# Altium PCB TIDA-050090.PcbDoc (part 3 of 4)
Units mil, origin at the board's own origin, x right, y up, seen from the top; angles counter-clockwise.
Board outline 4150 x 4140 mil, 8 copper layers (Top Layer 1, POWER1, GND1, SIGNAL1, SIGNAL2, GND2, POWER2, Bottom Layer 1), stack 60.703 mil thick; 130 components, 39 nets, 355 pads, 2292 vias.
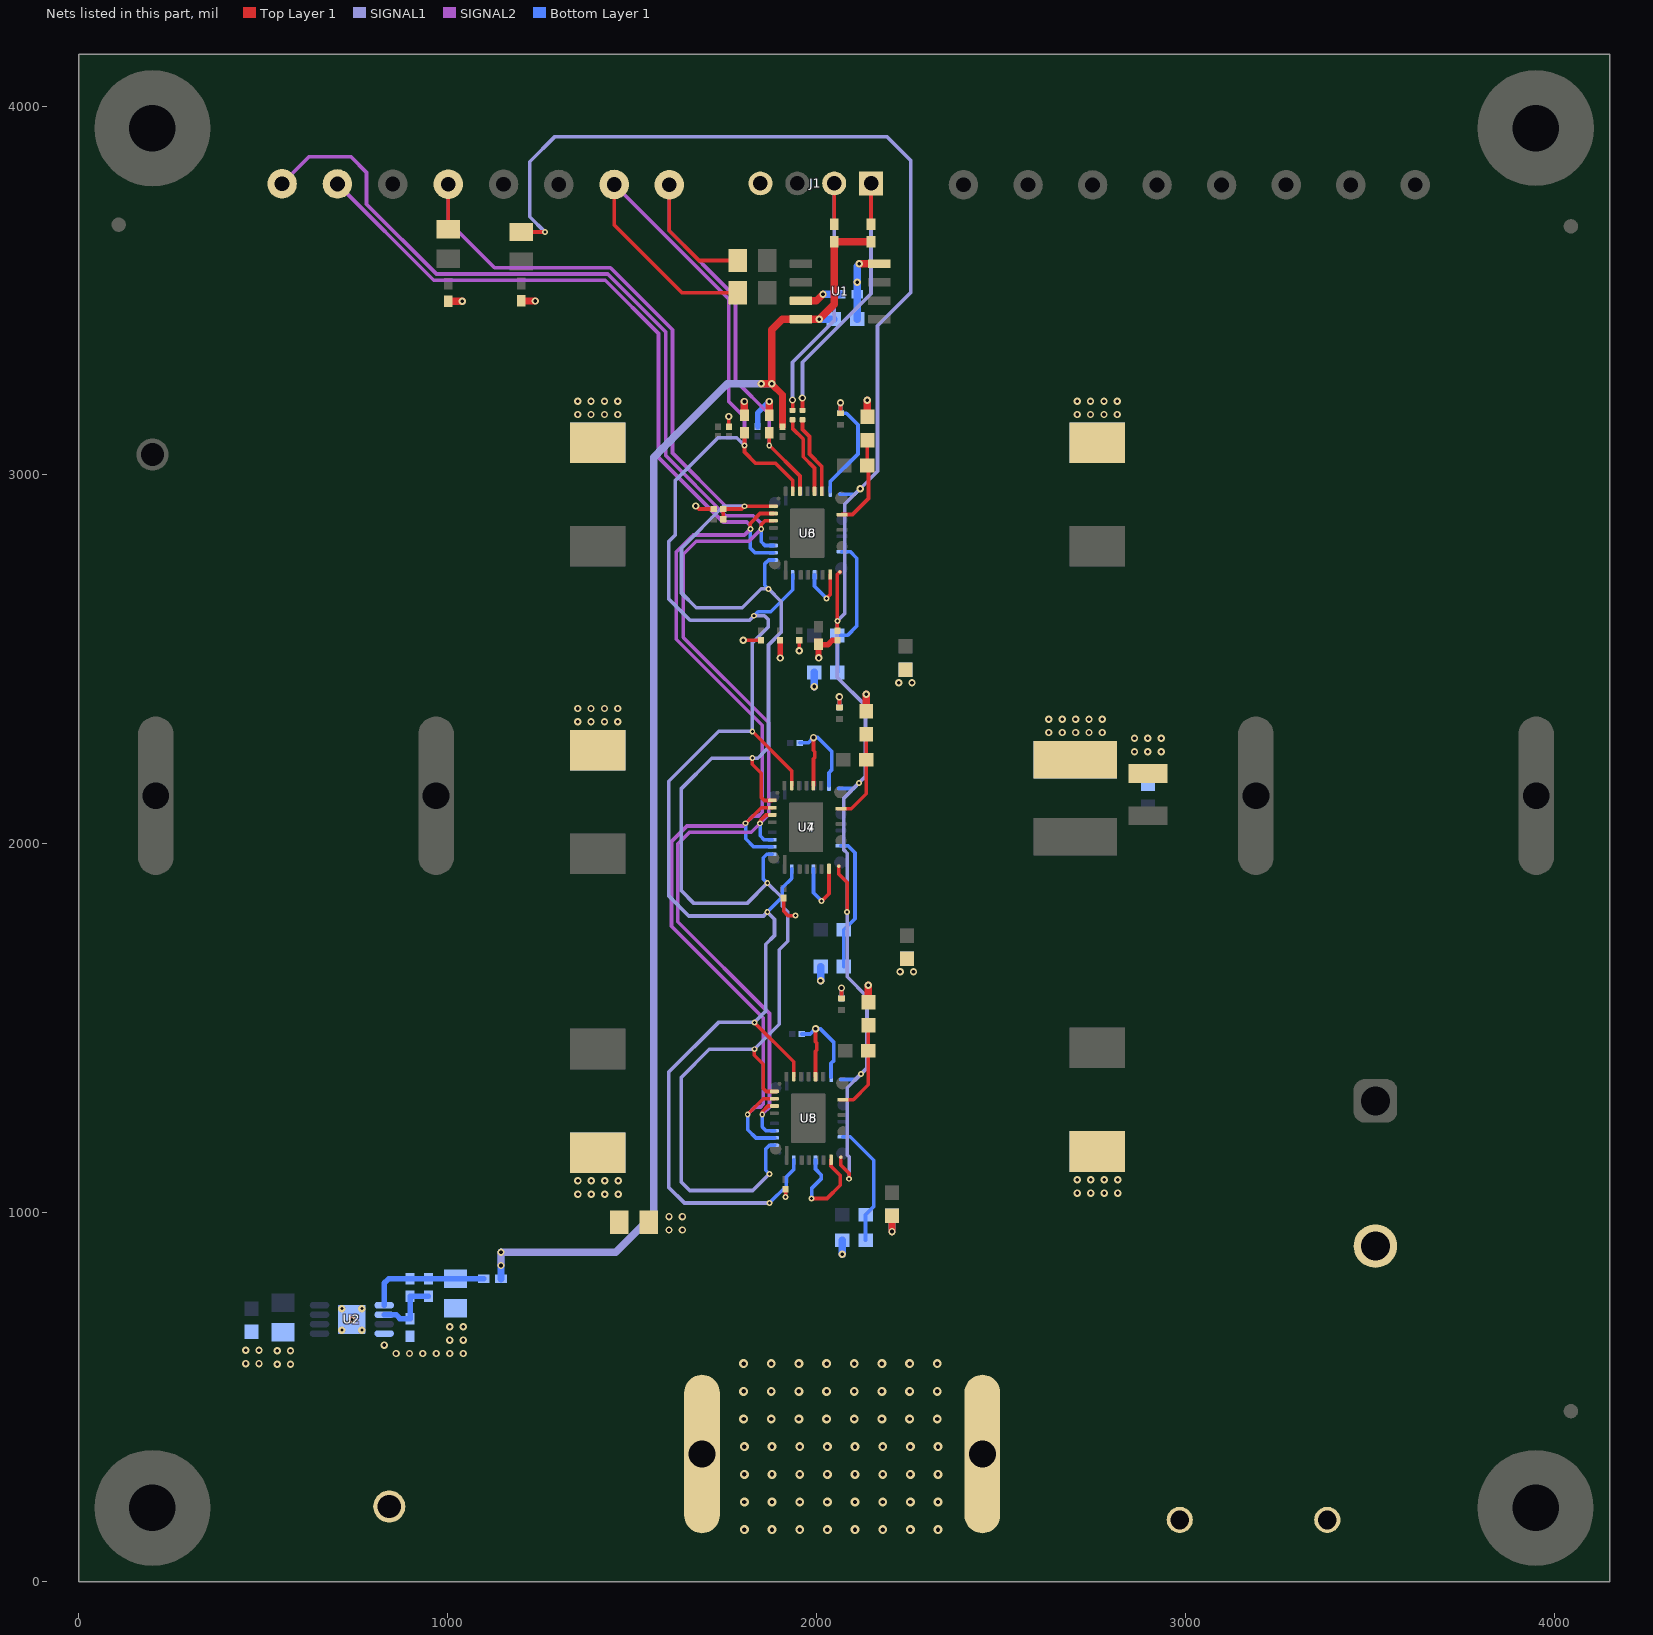
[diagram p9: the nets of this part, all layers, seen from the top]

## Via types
v1: diameter 24, hole 12, Top Layer 1 to Bottom Layer 1, tented both sides, 1740 vias
v2: diameter 20, hole 10, Top Layer 1 to Bottom Layer 1, tented both sides, 444 vias
v3: diameter 16, hole 8, Top Layer 1 to Bottom Layer 1, tented both sides, 67 vias
v4: diameter 19.68, hole 7.87, Top Layer 1 to Bottom Layer 1, tented both sides, 41 vias

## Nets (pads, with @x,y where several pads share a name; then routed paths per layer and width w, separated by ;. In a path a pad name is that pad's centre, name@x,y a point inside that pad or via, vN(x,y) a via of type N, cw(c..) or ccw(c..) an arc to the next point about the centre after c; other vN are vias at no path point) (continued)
ITIMER: C2.1 ITIMER1.1 NT1.1 U3.14 | length 1355.3
  Top Layer 1 w10: ITIMER1.1@1600.98,3786.57 1600.98,3662.17 1681.74,3581.41 NT1.1@1786.6,3581.41 ; C2.1@1872.04,3114.53 v3(1872.04,3080.35) 1955.31,2997.08 U3.14@1955.31,2955.69
  SIGNAL2 w10: ITIMER1.1@1600.98,3786.57 1600.98,3662.17 1780.4,3482.75 1780.4,3256.16 1872.04,3164.51 v3(1872.04,3080.35)
NetC6_1: C6.1 C7.1 R19.2 RZ2.2 U2.1 | length 334.2
  Bottom Layer 1 w15: U2.1@828.14,749.25 828.14,808.99 840.07,820.92 C6.1@898.24,820.92 R19.2@948.26,820.92 C7.1@1021.44,820.92 RZ2.2@1097.63,820.92
NetC6_2: C6.2 R19.1 R20.2 U2.2 | length 185.3
  Bottom Layer 1 w15: U2.2@828.14,723.66 860.27,723.66 870.98,712.95 R20.2@898.24,712.95 C6.2@898.24,773.68 R19.1@948.26,773.68
NetR23_2: R23.2 U3.12 | length 218.7
  Top Layer 1 w10: R23.2@1935.32,3149.76 1935.32,3125.86 1963.94,3097.24 1963.94,3049.72 1994.68,3018.98 U3.12@1994.68,2955.69
NetR24_2: R24.2 U3.11 | length 215.8
  Top Layer 1 w10: R24.2@1961.97,3149.76 1961.97,3123.25 1980.94,3104.28 1980.94,3056.76 2014.37,3023.33 U3.11@2014.37,2955.69
NetRZ1_2: RZ1.2 U1.7 | length 112.4
  Top Layer 1 w20: U1.7@1957.91,3472.53 2000,3472.53 v2(2017.71,3490.23)
  Bottom Layer 1 w20: v2(2017.71,3490.23) RZ1.2@2062.98,3490.23
OVP: NT4.1 OV1.1 R1.1 R11.2 U3.18 U4.18 U5.18 U6.18 U7.18 U8.18 | length 5503.5
  Top Layer 1 w10: NT4.1@1001.57,3666.22 1001.9,3666.55 OV1.1@1001.9,3788.49 ; R1.1@1747.28,2879.9 R11.2@1747.28,2907.71 1796.92,2907.71 v3(1804.54,2915.33) U3.18@1883.46,2915.33 ; v3(1826.01,2232.32) 1826.01,2215.9 1850.39,2191.53 1850.39,2125.84 1850.34,2125.8 1858.3,2117.83 U4.18@1880.51,2117.83 ; v3(1831.58,1443.38) 1831.58,1426.96 1855.95,1402.59 1855.95,1336.9 1855.91,1336.85 1863.87,1328.89 U5.18@1886.08,1328.89
  SIGNAL1 w10: v3(1804.54,2915.33) 1747.65,2915.33 1634.06,2801.74 1634.06,2679.82 1673.97,2639.91 1798.69,2639.91 1850.21,2691.43 v3(1869.67,2691.43) 1904.86,2656.25 1904.86,2574.15 1870.08,2539.37 1870.08,2261.71 1840.7,2232.32 v3(1826.01,2232.32) 1715.83,2232.32 1633.86,2150.36 1633.86,1872.68 1667.82,1838.72 1811.52,1838.72 v3(1866.73,1893.93) 1906.97,1853.69 1906.97,1830.84 1922.16,1815.66 1922.16,1735.77 1899.32,1712.94 1899.32,1511.12 v3(1831.58,1443.38) 1709.7,1443.38 1633.86,1367.54 1633.86,1082.77 1656.38,1060.25 1827.54,1060.25 v3(1872.28,1104.99)
  SIGNAL2 w10: OV1.1@1001.9,3788.49 1001.9,3687.45 1127.55,3561.79 1441.35,3561.79 1609.64,3393.5 1609.64,3059.71 1754.02,2915.33 v3(1804.54,2915.33)
  Bottom Layer 1 w10: v3(1866.73,1893.93) 1855.68,1904.99 1855.68,1962.32 1865.52,1972.17 U7.18@1880.53,1972.17 ; v3(1869.67,2691.43) 1859.65,2701.45 1859.65,2757.9 1859.65,2758.72 1860.62,2759.69 1860.62,2759.82 1870.46,2769.67 U6.18@1883.46,2769.67 ; v3(1872.28,1104.99) 1862.27,1115.01 1862.27,1173.05 1872.44,1183.22 U8.18@1886.08,1183.22
PGND: C5.2 C7.2 C20.2 C21.2 C22.1 C23.1 C24.2 C25.2 D1.2 D2.2 D3.2 D4.2 D5.2 D6.2 D7.2 D8.2 D9.2 D10.2 J5.1 R20.1 RCH1.2 TP2.1 U2.4 U2.9
  other v1: 1804.54,140.97 1879.54,140.97 1954.54,140.97 2029.54,140.97 2104.54,140.97 2179.54,140.97 2254.54,140.97 2329.54,140.97 1804.54,215.97 1879.54,215.97 1954.54,215.97 2029.54,215.97 2104.54,215.97 2179.54,215.97 2254.54,215.97 2329.54,215.97 1804.54,290.97 1879.54,290.97 1954.54,290.97 2029.54,290.97 2104.54,290.97 2179.54,290.97 2254.54,290.97 2329.54,290.97 1804.54,365.97 1879.54,365.97 1954.54,365.97 2029.54,365.97 2104.54,365.97 2179.54,365.97 2254.54,365.97 2329.54,365.97 1802.54,440.97 1877.54,440.97 1952.54,440.97 2027.54,440.97 2102.54,440.97 2177.54,440.97 2252.54,440.97 2327.54,440.97 1802.54,515.97 1877.54,515.97 1952.54,515.97 2027.54,515.97 2102.54,515.97 2177.54,515.97 2252.54,515.97 2327.54,515.97 1802.54,590.97 1877.54,590.97 1952.54,590.97 2027.54,590.97 2102.54,590.97 2177.54,590.97 2252.54,590.97 2327.54,590.97
  other v2: 537.91,589.48 574.25,589.48 452.63,591.16 488.97,591.16 860.43,618.54 896.78,618.54 933.12,618.54 969.47,618.54 1005.82,618.54 1042.16,618.54 537.91,625.83 574.25,625.83 452.63,627.5 488.97,627.5 828.14,641.33 1005.82,654.89 1042.16,654.89 1005.82,691.24 1042.16,691.24 1353.32,1050.19 1389.67,1050.19 1426.01,1050.19 1462.36,1050.19 2707.38,1053.36 2743.73,1053.36 2780.07,1053.36 2816.42,1053.36 1353.32,1086.53 1389.67,1086.53 1426.01,1086.53 1462.36,1086.53 2707.38,1089.7 2743.73,1089.7 2780.07,1089.7 2816.42,1089.7 2862.14,2249.66 2898.48,2249.66 2934.83,2249.66 2862.14,2286.01 2898.48,2286.01 2934.83,2286.01 2629.71,2301.9 2666.06,2301.9 2702.4,2301.9 2738.75,2301.9 2775.1,2301.9 1352.58,2330.75 1388.93,2330.75 1425.28,2330.75 1461.62,2330.75 2629.71,2338.25 2666.06,2338.25 2702.4,2338.25 2738.75,2338.25 2775.1,2338.25 1352.58,2367.09 1388.93,2367.09 1425.28,2367.09 1461.62,2367.09 1352.58,3163.94 1388.93,3163.94 1425.28,3163.94 1461.62,3163.94 2706.66,3163.94 2743,3163.94 2779.35,3163.94 2815.7,3163.94 1352.58,3200.28 1388.93,3200.28 1425.28,3200.28 1461.62,3200.28 2706.66,3200.28 2743,3200.28 2779.35,3200.28 2815.7,3200.28
  other v4: 713.38,681.73 767.71,681.73 740.54,710.86 713.38,740 767.71,740
PGOOD: PGOOD1.1 U3.19 U4.19 U5.19 U6.19 U7.19 U8.19 | length 4520.8
  Top Layer 1 w10: v3(1808.08,2055.87) 1850.35,2098.15 U4.19@1880.51,2098.15 ; v3(1813.63,1266.93) 1855.91,1309.21 U5.19@1886.08,1309.21 ; v3(1820.86,2853.37) 1820.86,2869.45 1847.06,2895.65 U3.19@1883.46,2895.65
  SIGNAL2 w10: PGOOD1.1@701.45,3788.96 962.62,3527.79 1427.27,3527.79 1571.71,3383.35 1571.71,3047.55 1746.92,2872.34 1811.02,2872.34 1820.86,2862.5 v3(1820.86,2853.37) 1804.65,2837.17 1666.87,2837.17 1663.78,2834.08 1662.95,2834.08 1620.06,2791.19 1620.06,2554.72 1853.05,2321.73 1853.05,2086.03 1842.84,2075.83 1828.03,2075.83 v3(1808.08,2055.87) 1800.93,2048.73 1648.93,2048.73 1607.01,2006.81 1607.01,1776.58 1855.55,1528.04 1855.55,1294.04 1848.4,1286.88 1833.58,1286.88 v3(1813.63,1266.93)
  Bottom Layer 1 w10: v3(1808.08,2055.87) 1808.08,2014.01 1830.24,1991.85 U7.19@1880.53,1991.85 ; v3(1813.63,1266.93) 1813.63,1225.07 1835.79,1202.91 U8.19@1886.08,1202.91 ; v3(1820.86,2853.37) 1820.86,2801.67 1833.18,2789.35 U6.19@1883.46,2789.35
PMBUS_SCL: J1.2 R14.1 R23.1 | length 773.1
  Top Layer 1 w10: R23.1@1935.32,3175.35 v2@1935.32,3203.74 ; R14.1@2048.02,3679.86 J1.2@2048.02,3790.57
  SIGNAL1 w10: v2(1934.97,3203.38) 1934.97,3305.91 2048.02,3418.97 J1.2@2048.02,3790.57
PMBUS_SDA: J1.1 R13.1 R24.1 | length 802.9
  Top Layer 1 w10: R24.1@1961.97,3175.35 v2(1961.97,3208.74) ; R13.1@2148.02,3679.96 J1.1@2148.02,3790.57
  SIGNAL1 w10: v2(1961.97,3208.74) 1961.97,3305.37 2011.62,3355.02 2148.02,3491.42 J1.1@2148.02,3790.57
QGND1: C1.2 C2.2 C3.2 C4.2 C8.1 C9.1 C10.2 C11.2 C12.2 C13.2 C14.1 C15.1 C16.2 C17.2 C18.2 C19.2 C26.1 C27.1 C28.2 C29.2 C30.2 C31.2 J1.4 J2.1 J2.2 R3.1 R4.1 R5.1 R6.1 R7.1 R8.1 R9.1 R10.1 R11.1 R12.1 R15.1 R17.1 R18.1 RCH1.1 RZ1.1 U1.4 U3.5 U4.5 U4.12 U5.5 U5.12 U6.5 U6.12 U7.5 U7.12 U8.5 U8.12 | length 2919.6
  Top Layer 1 w10: v2(1672.49,2915.98) 1680.76,2907.71 R11.1@1721.29,2907.71 ; R12.1@1762.39,3130.59 v2@1762.39,3158.97 ; v2(1801.18,2551.86) R4.1@1850,2551.86 ; R7.1@1911.02,1853.12 1911.02,1817.64 1923.19,1805.47 v3(1943.63,1805.47) ; v3(1916.59,1042.22) R5.1@1916.59,1064.17 ; v2@1953.35,2523.48 R3.1@1953.35,2551.86 ; v3(1986.85,1038.85) 2028.73,1038.85 2064.3,1074.42 2064.3,1101.17 2039.62,1125.85 U5.5@2039.62,1143.85 ; U4.12@1991.73,2158.19 1991.73,2230.6 1995.39,2234.26 1995.39,2250 1991.73,2253.66 1991.73,2287.86 v2(1992.09,2288.21) ; U5.12@1997.3,1369.25 1997.3,1437.18 2000.94,1440.82 2000.94,1461.05 1997.64,1464.36 v2(1997.64,1499.27) ; v3(2014.14,1845.09) 2034.06,1865.01 U4.5@2034.06,1932.8 ; v3(2027.55,2665.59) 2037.01,2675.05 U3.5@2037.01,2730.3 ; C9.1@2062.29,2370.06 v2(2062.29,2398.38) ; C8.1@2065.25,3167.56 v2(2065.25,3195.88) ; C14.1@2067.86,1581.11 v2(2067.86,1609.44)
  Top Layer 1 w15: v2(1901.67,2503.8) R10.1@1901.67,2551.86 ; v2@2005.49,2503.8 C1.2@2005.49,2541.23 2006.87,2539.86 2030.71,2539.86 2042.72,2551.86 R15.1@2056.69,2551.86
  Top Layer 1 w20: R18.1@1001.57,3470.71 v2(1039.56,3470.71) ; R17.1@1199.55,3471.84 v2(1237.54,3471.84) ; C3.2@1804.68,3161.77 v2(1804.68,3199.2) ; C2.2@1872.04,3161.77 v2(1872.04,3199.2) ; v2(2116.38,3572.53) U1.4@2170.51,3572.53 ; C13.2@2135.13,2359.89 v2(2135.13,2405.49) ; C12.2@2138.08,3157.39 v2(2138.08,3202.99) ; C18.2@2140.69,1570.95 v2(2140.69,1616.55) ; v2(2204.87,949.05) C16.2@2204.87,991.49
  Bottom Layer 1 w10: R6.1@1954.74,2273.8 1977.67,2273.8 v2(1992.09,2288.21) 2003.77,2288.21 2041.05,2250.93 2041.05,2200.06 2034.07,2193.07 U7.5@2034.07,2157.2 ; R9.1@1960.29,1484.86 1983.23,1484.86 v2(1997.64,1499.27) 2009.61,1499.27 2047.25,1461.63 2047.25,1412.67 2039.62,1405.05 U8.5@2039.62,1368.26 ; v3(1986.85,1038.85) 1986.85,1065.84 2012.64,1091.63 2012.64,1103.13 1997.3,1118.47 U8.12@1997.3,1142.87 ; U7.12@1991.75,1931.81 1991.75,1867.48 v3(2014.14,1845.09) ; U6.12@1994.68,2729.31 1994.69,2698.45 v3(2027.55,2665.59) ; U6.5@2037.01,2954.7 2037.01,2981.45 2112.65,3057.09 2112.65,3136.06 2081.16,3167.56 C15.1@2065.25,3167.56 v2(2065.25,3195.88) ; C26.1@2062.29,2370.06 v2(2062.29,2398.38) ; C27.1@2067.86,1581.11 v2(2067.86,1609.44)
  Bottom Layer 1 w15: R8.1@1840.51,3131.45 1840.51,3167.67 v2(1872.04,3199.2)
  Bottom Layer 1 w20: v2(1993.7,2426.45) C19.2@1993.7,2464.8 ; v2(2011.16,1629.35) C30.2@2011.16,1667.7 ; v2(2070.13,887.23) C31.2@2070.13,925.59 ; C4.2@2110.23,3422.53 RZ1.1@2110.23,3490.23 v2(2110.23,3522.53) 2110.23,3566.38 v2(2116.38,3572.53) ; v2(2204.87,949.05) C29.2@2204.87,991.49
  other v2: 1600.27,953.36 1636.61,953.36 1600.27,989.71 1636.61,989.71 2226.66,1653.05 2263.01,1653.05 2222.73,2437.2 2259.07,2437.2 2005.85,2504.16 1953.7,2523.83 1762.04,3158.62
SFT_SEL: NT3.1 R15.2 U3.6 U4.6 U5.6 U6.6 U7.6 U8.6 | length 4855.9
  Top Layer 1 w10: NT3.1@1199.55,3658.69 v3(1264.37,3658.69) ; R15.2@2056.69,2577.85 v3(2056.69,2604.23) 2056.69,2730.3 U3.6@2063.58,2737.19 ; U4.6@2060.63,1939.68 2060.63,1918.06 2083.19,1895.5 v3(2083.19,1815.77) ; U5.6@2066.2,1150.74 2066.2,1129.11 2088.76,1106.55 v3(2088.76,1092.11)
  SIGNAL1 w10: v3(1264.37,3658.69) 1222.68,3700.38 1222.68,3849.02 1290.98,3917.32 2190.7,3917.32 2255.47,3852.56 2255.47,3494.69 2165.35,3404.57 2165.35,3009.89 v2(2118.39,2962.93) 2076.77,2921.31 2076.77,2624.31 v3(2056.69,2604.23) 2056.69,2451.18 2132.75,2375.13 2132.75,2182.72 v3(2115.46,2165.43) 2074.34,2124.31 2074.34,1983.49 2083.19,1974.64 v3(2083.19,1815.77) 2083.19,1639.65 2137.1,1585.74 2137.1,1392.58 v3(2121.01,1376.49) 2083.36,1338.84 2083.36,1156.83 2088.76,1151.44 v3(2088.76,1092.11)
  Bottom Layer 1 w10: U7.6@2060.65,2150.31 2100.34,2150.32 v3(2115.46,2165.43) ; U6.6@2063.58,2947.81 2103.28,2947.82 v2(2118.39,2962.93) ; U8.6@2066.2,1361.37 2105.89,1361.37 v3(2121.01,1376.49)
SWEN: SWEN1.1 U3.20 U4.20 U5.20 U6.20 U7.20 U8.20 | length 4526.6
  Top Layer 1 w10: v3(1847.45,2055.83) v3(1847.45,2055.83) 1847.5,2063.08 1862.88,2078.46 U4.20@1880.51,2078.46 ; v3(1850.39,2853.33) v3(1850.39,2853.33) 1850.43,2865.8 1860.6,2875.96 U3.20@1883.46,2875.96 ; v3(1853,1266.88) 1853.05,1266.93 1853.05,1274.13 1868.44,1289.52 U5.20@1886.08,1289.52
  SIGNAL2 w10: SWEN1.1@551.45,3789.4 624.48,3862.44 738.18,3862.44 780.45,3820.16 780.45,3734 969.66,3544.79 1434.31,3544.79 1591.16,3387.95 1591.16,3052.9 1754.3,2889.75 1828.98,2889.75 1850.39,2868.34 v3(1850.39,2853.33) 1817.23,2820.17 1673.92,2820.17 1639.04,2785.29 1639.04,2559.79 1870.74,2328.08 1870.74,2079.12 v3(1847.45,2055.83) 1823.35,2031.73 1655.97,2031.73 1624.01,1999.76 1624.01,1789.02 1872.55,1540.47 1872.55,1287 1855.44,1269.88 1853,1269.88 v3(1853,1266.88)
  Bottom Layer 1 w10: v3(1847.45,2055.83) 1847.45,2021.77 1857.68,2011.54 U7.20@1880.53,2011.54 ; v3(1850.39,2853.33) 1850.39,2819.27 1860.62,2809.04 U6.20@1883.46,2809.04 ; v3(1853,1266.88) 1853,1232.83 1863.24,1222.59 U8.20@1886.08,1222.59
TEMP: C3.1 NT2.1 TEMP1.1 U3.15 U4.15 U5.15 U6.15 U7.15 U8.15 | length 5767.7
  Top Layer 1 w10: TEMP1.1@1451.62,3787.49 1451.62,3677.55 1635.39,3493.79 NT2.1@1786.6,3493.79 ; C3.1@1804.68,3114.53 v3(1804.68,3080.35) 1804.68,3062.1 1835.29,3031.5 1889.37,3031.5 1935.63,2985.24 U3.15@1935.63,2955.69 ; v3(1826.01,2305.02) 1932.68,2198.36 U4.15@1932.68,2158.19 ; v3(1831.58,1516.07) 1938.24,1409.41 U5.15@1938.24,1369.25
  SIGNAL1 w10: v3(1804.68,3080.35) 1783.92,3101.12 1733.01,3101.12 1617.06,2985.17 1617.06,2837.54 1599.29,2819.76 1599.29,2664.08 1657.45,2605.91 1818.52,2605.91 v3(1831.02,2618.41) 1858.84,2618.41 1869.67,2607.58 1869.67,2588.57 1826.01,2544.91 v3(1826.01,2305.02) 1735.28,2305.02 1599.86,2169.6 1599.86,1858.6 1653.74,1804.72 1856.26,1804.72 v3(1866.73,1815.19) 1886.16,1795.76 1886.16,1751.69 1862.56,1728.09 1862.56,1547.05 v3(1831.58,1516.07) 1734.31,1516.07 1599.86,1381.62 1599.86,1068.69 1642.29,1026.25 v3(1872.28,1026.25)
  SIGNAL2 w10: TEMP1.1@1451.62,3787.49 1762.04,3477.07 1762.04,3199.2 1804.68,3156.56 v3(1804.68,3080.35)
  Bottom Layer 1 w10: v3(1831.02,2618.41) 1841.83,2629.23 1875.94,2629.23 1935.63,2688.92 U6.15@1935.63,2729.31 ; v3(1866.73,1815.19) 1907.58,1856.04 1907.58,1881.37 1932.69,1906.48 U7.15@1932.69,1931.81 ; v3(1872.28,1026.25) 1918.01,1071.98 1918.01,1097.31 1938.24,1117.54 U8.15@1938.24,1142.87
VCC_3v3: C4.1 R13.2 R14.2 R16.2 RZ2.1 U1.8 | length 3830.5
  Top Layer 1 w18: v2(1878.39,3246.97) 1907.91,3217.44 R16.2@1907.91,3130.59
  Top Layer 1 w20: v2(1850.12,3246.97) v2(1878.39,3246.97) 1878.39,3394.13 1906.78,3422.53 U1.8@1957.91,3422.53 v2(2007.87,3422.53) 2048.02,3462.68 R14.2@2048.02,3632.62 2048.12,3632.71 R13.2@2148.02,3632.71
  SIGNAL1 w20: v2(1144.87,856.93) v2(1144.87,893.28) 1456.22,893.28 1558.93,995.98 1558.93,3047.78 1758.12,3246.97 v2(1850.12,3246.97) v2(1878.39,3246.97)
  Bottom Layer 1 w20: RZ2.1@1144.87,820.92 v2(1144.87,856.93) v2(1144.87,893.28) ; v2(2007.87,3422.53) C4.1@2047.24,3422.53
VDD_efuse1: C12.1 R21.1 U3.9 | length 249.2
  Top Layer 1 w10: U3.9@2069.49,2892.7 2097.53,2892.7 2141.3,2936.47 2141.3,3022.28 R21.1@2138.08,3025.51 C12.1@2138.08,3094.4
VDD_efuse2: C18.1 R25.1 U5.9 | length 246.5
  Top Layer 1 w10: U5.9@2072.1,1306.25 2100.15,1306.25 2140.69,1346.8 R25.1@2140.69,1439.06 C18.1@2140.69,1507.96
VDD_efuse3: C30.1 R27.1 U7.9 | length 366.2
  Bottom Layer 1 w10: U7.9@2066.55,1994.8 2085.31,1994.8 2104.25,1975.86 2104.25,1797.06 R27.1@2074.15,1766.96 C30.1@2074.15,1667.7
VDD_efuse4: C13.1 R22.1 U4.9 | length 246.5
  Top Layer 1 w10: U4.9@2066.54,2095.2 2094.58,2095.2 2135.13,2135.75 R22.1@2135.13,2228.01 C13.1@2135.13,2296.9
VDD_efuse5: C19.1 R26.1 U6.9 | length 393.5
  Bottom Layer 1 w10: R26.1@2057.03,2565.19 2083.85,2565.19 2109.52,2590.86 2109.52,2774.54 2091.76,2792.3 U6.9@2069.49,2792.3 ; C19.1@2057.09,2465.2 R26.1@2057.09,2564.46
VDD_efuse6: C31.1 R28.1 U8.9 | length 335.7
  Bottom Layer 1 w10: U8.9@2072.1,1205.86 2091.94,1205.86 2155.51,1142.28 2155.51,1016.87 R28.1@2133.13,994.48 C31.1@2133.13,925.59
pads on no net: FID1.1 FID2.1 FID3.1 H1.1 H2.1 H3.1 H4.1 H5.0 H6.0 H7.0 H8.0 LBL1.0 U1.1 U1.2 U1.3 U2.3 U2.6 U2.7 U3.17 U3.21 U4.11 U4.14 U4.17 U4.21 U5.11 U5.14 U5.17 U5.21 U6.11 U6.14 U6.17 U6.21 U7.11 U7.14 U7.17 U7.21 U8.11 U8.14 U8.17 U8.21

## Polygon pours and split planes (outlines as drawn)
Efuse_OUT on Top Layer 1 "EFUSE_OUT_L01_P030" (solid, remove dead copper, pour order 30): 2112.88,1299.02 2091.28,1277.41 2061.94,1277.41 2052.89,1268.37 2052.89,1191.13 2059.08,1184.95 2089.86,1184.95 2112.88,1161.92 2112.88,1054.78 2038.21,980.1 2038.21,33.03 2051.32,19.92 4044.62,19.92 4108.4,83.7 4108.4,4025.6 4017.58,4116.42 2134.47,4116.42 2106.89,4088.84 2106.89,2882.09 2088.66,2863.86 2059.32,2863.86 2050.28,2854.81 2050.28,2777.58 2075.59,2752.27 2075.59,2465.31 2104.96,2434.65 2104.96,2085.61 2085.71,2066.36 2056.37,2066.36 2047.32,2057.31 2047.32,1980.08 2058.49,1980.08 2098.55,1940.01 2098.55,1629.27 2112.88,1614.94
Efuse_IN on Top Layer 1 "EFUSE_IN_L01_P029" (solid, remove dead copper, pour order 29): 2089.04,1901.27 2089.04,1615.96 2098.55,1606.45 2098.55,1332.47 2085.14,1319.05 2050.36,1319.05 2024.4,1293.09 2024.4,32.13 2011.66,19.39 53.59,19.39 23.76,49.22 23.76,4064.95 72.98,4114.17 2080.85,4114.17 2095.59,4099.43 2095.59,3057.01 2095.59,2918.57 2082.52,2905.49 2053.5,2905.49 2028.57,2880.56 2028.57,2761.73 2061.79,2728.5 2061.79,2462.21 2092.64,2431.36 2092.64,2121.07 2079.57,2107.99 2044.79,2107.99 2020.39,2083.59 2020.39,1969.93
PGND on Top Layer 1 "PGND_L01_P000" (solid, remove dead copper, pour order 0): 2480.31,634.64 1681.48,634.64 1624.01,577.17 1624.01,109.14 1675.51,57.64 2488.5,57.64 2519.68,88.82 2519.68,595.27
Efuse_OUT on Bottom Layer 1 "EFUSE_OUT_L08_P046" (solid, remove dead copper, pour order 46): 2112.65,3399.02 2112.65,4088.84 2137.98,4114.17 4063.6,4114.17 4114.16,4063.61 4114.16,59.28 4084.41,29.53 2103.25,29.53 2070.6,62.17 2070.6,864.67 2170.34,964.41 2170.34,1144.04 2091.53,1222.85 2062.47,1222.85 2052.86,1232.45 2052.86,1324.66 2055.56,1327.36 2077.5,1327.36 2118.58,1368.44 2118.58,1982.01 2088.8,2011.79 2056.91,2011.79 2047.31,2021.39 2047.31,2113.6 2050.01,2116.3 2070.6,2116.3 2121.52,2167.22 2121.52,2779.51 2091.74,2809.29 2059.85,2809.29 2050.24,2818.89 2050.24,2911.1 2052.93,2913.79 2082.11,2913.79 2112.65,2944.33
Efuse_IN on Bottom Layer 1 "EFUSE_IN_L08_P045" (solid, remove dead copper, pour order 45): 29.52,4045.27 98.43,4114.17 2087.32,4114.17 2102.01,4099.48 2102.01,2985.43 2027.55,2910.97 2027.55,2790.53 2038.57,2779.51 2093.39,2779.51 2102.18,2770.72 2102.18,2188.1 2025.64,2111.57 2025.64,1991.98 2035.62,1982.01 2088.34,1982.01 2102.18,1968.17 2102.18,1397.35 2026.15,1321.32 2026.15,1207.49 2040.58,1193.06 2092.86,1193.06 2147.26,1138.67 2147.26,957.18 2096.31,906.24 2057.08,867.15 2057.08,59.05 2027.56,29.53 59.05,29.53 29.52,59.06
PGND on Bottom Layer 1 "PGND_L08_P028" (solid, remove dead copper, pour order 28): 2480.31,634.64 1681.48,634.64 1624.01,577.17 1624.01,109.14 1675.51,57.64 2488.5,57.64 2519.68,88.82 2519.68,595.27
Efuse_OUT on SIGNAL2 "EFUSE_OUT_L05_P039" (solid, remove dead copper, pour order 39): 2043.97,869.56 2064.26,889.86 2500.31,889.86 2529.52,919.06 2529.52,3384.06 2564.99,3419.53 4045.27,3419.53 4114.16,3350.63 4114.16,73.85 4066.19,25.87 2056.69,25.87 2043.97,38.6
QGND1 on SIGNAL2 "QGND1_L05_P038" (solid, remove dead copper, pour order 38): 2632.85,934.98 2798.09,934.98 2800.51,932.56 3250.78,482.28 3491.08,482.28 3513.78,459.59 3513.78,146.65 3465.55,98.43 2687.01,98.43 2598.43,187.01 2598.43,578.42 2385.27,791.57 1109.59,791.57 1070.22,830.94 1070.22,929.37 1093.63,952.78 1398.75,952.78 1515.74,1069.77 1515.74,3373.49 1450.02,3439.21 419.49,3439.21 393.69,3465.01 393.69,4035.42 462.6,4104.33 3651.57,4104.33 3720.47,4035.43 3720.47,3464.57 3695.12,3439.21 2566.91,3439.21 2518.5,3390.8 2518.5,1049.09
Efuse_IN on SIGNAL2 "EFUSE_IN_L05_P040" (solid, remove dead copper, pour order 40): 1591,890 1483.16,782.15 1105.69,782.15 1060.8,827.04 1060.8,933.27 1090.51,962.97 1394.53,962.97 1505.9,1073.99 1505.9,3369.54 1460.93,3414.51 73.72,3414.51 29.52,3370.31 29.52,93.43 102.16,20.79 2018.82,20.79 2030.17,32.13 2030.17,873.58 2013.75,890
Efuse_OUT on POWER1 "EFUSE_OUT_L02_P032" (solid, remove dead copper, pour order 32): 2053.51,1191.13 2059.08,1185.57 2059.08,45.45 2079.89,24.64 4035.39,24.64 4114.16,103.41 4114.16,4035.44 4033.19,4116.42 2140.23,4116.42 2112.65,4088.84 2112.65,2888.03 2090.34,2865.73 2088.47,2863.86 2059.32,2863.86 2050.28,2854.81 2050.28,2777.58 2056.46,2771.39 2089.03,2771.39 2110.72,2749.7 2110.72,2091.13 2086.68,2067.09 2057.1,2067.09 2047.32,2057.31 2047.32,1980.08 2053.51,1973.89 2086.08,1973.89 2118.64,1941.32 2118.64,1304.78 2091.25,1277.44 2091.23,1277.41 2061.94,1277.41 2053.51,1268.98
Efuse_IN on POWER1 "EFUSE_IN_L02_P031" (solid, remove dead copper, pour order 31): 2103.97,1332.12 2103.97,1300.37 2087.5,1283.9 2058.91,1283.9 2045.07,1270.06 2045.07,47.04 2023.52,25.49 112.01,25.49 29.52,107.98 29.52,4064.95 78.74,4114.17 2086.61,4114.17 2101.36,4099.43 2101.36,3057.01 2101.36,2918.57 2101.36,2886.82 2084.88,2870.34 2056.3,2870.34 2042.45,2856.5 2042.45,2768.51 2052.03,2758.93 2084.61,2758.93 2098.4,2745.14 2098.4,2089.3 2081.95,2072.84 2053.36,2072.84 2039.52,2059 2039.52,1971.63 2049.71,1961.43 2086.51,1961.43 2104.74,1943.2 2104.74,1332.89
PGND on GND2 "PGND_L06_P042" (solid, remove dead copper, pour order 42): 102.19,4114.17 4045.28,4114.17 4114.16,4045.28 4114.16,78.73 4064.96,29.53 83.62,29.53 29.52,83.63 29.52,4041.5
QGND1 on GND2 "QGND1_L06_P041" (solid, remove dead copper, pour order 41): 2632.85,934.98 2798.09,934.98 2800.51,932.56 3250.78,482.28 3491.08,482.28 3513.78,459.59 3513.78,146.65 3465.55,98.43 2687.01,98.43 2598.43,187.01 2598.43,578.42 2385.27,791.57 1109.59,791.57 1070.22,830.94 1070.22,929.37 1093.63,952.78 1398.75,952.78 1515.74,1069.77 1515.74,3373.49 1450.02,3439.21 509.2,3439.21 459.99,3488.42 459.99,3893.73 487.75,3921.49 3617.65,3921.49 3690.94,3848.2 3690.94,3498.27 3631.88,3439.21 2566.91,3439.21 2518.5,3390.8 2518.5,1049.09
PGND on GND1 "PGND_L03_P034" (solid, remove dead copper, pour order 34): 102.19,4114.17 4045.28,4114.17 4114.16,4045.28 4114.16,78.73 4064.96,29.53 83.62,29.53 29.52,83.63 29.52,4041.5
QGND1 on GND1 "QGND1_L03_P033" (solid, remove dead copper, pour order 33): 2632.85,934.98 2798.09,934.98 2800.51,932.56 3250.78,482.28 3491.08,482.28 3513.78,459.59 3513.78,146.65 3465.55,98.43 2687.01,98.43 2598.43,187.01 2598.43,578.42 2385.27,791.57 1109.59,791.57 1070.22,830.94 1070.22,929.37 1093.63,952.78 1398.75,952.78 1515.74,1069.77 1515.74,3373.49 1450.02,3439.21 509.2,3439.21 459.99,3488.42 459.99,3893.73 487.75,3921.49 3617.65,3921.49 3690.94,3848.2 3690.94,3498.27 3631.88,3439.21 2566.91,3439.21 2518.5,3390.8 2518.5,1049.09
Efuse_OUT on POWER2 "EFUSE_OUT_L07_P044" (solid, remove dead copper, pour order 44): 2118.58,1368.44 2077.5,1327.36 2055.56,1327.36 2052.86,1324.66 2052.86,1232.45 2062.47,1222.85 2091.53,1222.85 2128.53,1185.85 2128.53,922.6 2070.6,864.67 2070.6,53.97 2098.7,25.87 4056.34,25.87 4114.16,83.7 4114.16,4025.6 4025.59,4114.17 2137.98,4114.17 2112.65,4088.84 2112.65,2944.33 2082.11,2913.79 2052.93,2913.79 2050.24,2911.1 2050.24,2818.89 2059.85,2809.29 2091.74,2809.29 2121.52,2779.51 2121.52,2167.22 2070.6,2116.3 2050.01,2116.3 2047.31,2113.6 2047.31,2021.39 2056.91,2011.79 2088.8,2011.79 2118.58,1982.01
Efuse_IN on POWER2 "EFUSE_IN_L07_P043" (solid, remove dead copper, pour order 43): 2113.44,923.37 2096.31,906.24 2057.08,867.15 2057.08,59.05 2018.82,20.79 67.79,20.79 29.52,59.06 29.52,4055.11 88.58,4114.17 2086.61,4114.17 2102.01,4098.78 2102.01,2985.43 2027.55,2910.97 2027.55,2790.53 2038.57,2779.51 2093.39,2779.51 2102.18,2770.72 2102.18,2188.1 2025.64,2111.57 2025.64,1991.98 2035.62,1982.01 2088.34,1982.01 2102.18,1968.17 2102.18,1397.35 2026.15,1321.32 2026.15,1207.49 2040.58,1193.06 2092.86,1193.06 2113.44,1172.48
Efuse_OUT on SIGNAL1 "EFUSE_OUT_L04_P036" (solid, remove dead copper, pour order 36): 2043.97,869.56 2064.26,889.86 2500.31,889.86 2529.52,919.06 2529.52,3384.06 2564.99,3419.53 4045.27,3419.53 4114.16,3350.63 4114.16,73.85 4066.19,25.87 2056.69,25.87 2043.97,38.6
QGND1 on SIGNAL1 "QGND1_L04_P035" (solid, remove dead copper, pour order 35): 2632.85,934.98 2798.09,934.98 2800.51,932.56 3250.78,482.28 3491.08,482.28 3513.78,459.59 3513.78,146.65 3465.55,98.43 2687.01,98.43 2598.43,187.01 2598.43,578.42 2385.27,791.57 1109.59,791.57 1070.22,830.94 1070.22,929.37 1093.63,952.78 1398.75,952.78 1515.74,1069.77 1515.74,3373.49 1450.02,3439.21 419.49,3439.21 393.69,3465.01 393.69,4035.42 462.6,4104.33 3651.57,4104.33 3720.47,4035.43 3720.47,3464.57 3695.12,3439.21 2566.91,3439.21 2518.5,3390.8 2518.5,1049.09
Efuse_IN on SIGNAL1 "EFUSE_IN_L04_P037" (solid, remove dead copper, pour order 37): 1591,890 1483.16,782.15 1105.69,782.15 1060.8,827.04 1060.8,933.27 1090.51,962.97 1394.53,962.97 1505.9,1073.99 1505.9,3369.54 1460.93,3414.51 73.72,3414.51 29.52,3370.31 29.52,93.43 102.16,20.79 2018.82,20.79 2030.17,32.13 2030.17,873.58 2013.75,890

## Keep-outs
Keep-Out Layer:
  text ".Layer_Name" at 572.49,-1004.76 h60

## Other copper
Top Layer 1:
  pour cut-out: 4000.27,462.05 cw(c4045.27,462.05) 4045.27,507.05 cw(c4045.27,462.05) 4090.27,462.05 cw(c4045.27,462.05) 4045.27,417.05 cw(c4045.27,462.05)
  pour cut-out: 63.26,3678.58 cw(c108.26,3678.58) 108.26,3723.58 cw(c108.26,3678.58) 153.26,3678.58 cw(c108.26,3678.58) 108.26,3633.58 cw(c108.26,3678.58)
  pour cut-out: 4000.27,3674.15 cw(c4045.27,3674.15) 4045.27,3719.15 cw(c4045.27,3674.15) 4090.27,3674.15 cw(c4045.27,3674.15) 4045.27,3629.15 cw(c4045.27,3674.15)
  region net QGND1: 2218.4,2492.36 2209.85,2483.81 2209.85,2428.49 2216.7,2421.65 2268.53,2421.65 2275.75,2428.87 2275.75,2485.14 2268.53,2492.36
  region net QGND1: 2222.34,1708.21 2213.79,1699.66 2213.79,1644.34 2220.64,1637.5 2272.47,1637.5 2279.69,1644.72 2279.69,1700.99 2272.47,1708.21
  region net QGND1: 1530.11,1023.27 1520.9,1014.05 1520.9,929.53 1525.58,924.84 1644.32,924.84 1653.53,934.05 1653.53,1013.42 1643.69,1023.27
  region net PGND: 1486.21,3025.82 1328.73,3025.82 1318.89,3035.67 1318.89,3218.93 1342.31,3242.36 1476.37,3242.36 1496.05,3222.68 1496.05,3035.67
  region net PGND: 2840.29,3025.82 2682.81,3025.82 2672.96,3035.67 2672.96,3218.93 2696.39,3242.36 2830.45,3242.36 2850.13,3222.68 2850.13,3035.67
  region net PGND: 1496.05,914.21 1481.68,899.84 1367.47,899.84 1318.89,948.42 1318.89,1214.8 1328.73,1224.64 1486.21,1224.64 1496.05,1214.8
  region net PGND: 2682.79,1227.81 2840.27,1227.81 2850.11,1217.97 2850.11,1034.7 2826.69,1011.28 2692.63,1011.28 2672.95,1030.96 2672.95,1217.97
  region net PGND: 1486.21,2192.64 1328.73,2192.64 1318.89,2202.48 1318.89,2385.75 1342.31,2409.17 1476.37,2409.17 1496.05,2389.49 1496.05,2202.48
  region net PGND: 2621.07,2360.31 2921.02,2360.31 2951.82,2329.5 2951.82,2164.91 2945.18,2158.26 2645.44,2158.26 2603.36,2200.34 2603.36,2342.6
  region net Efuse_OUT: 2840.27,1385.3 2682.79,1385.3 2672.95,1395.14 2672.95,1578.41 2696.37,1601.83 2830.43,1601.83 2850.11,1582.15 2850.11,1395.14
  region net Efuse_OUT: 2682.81,2868.34 2840.29,2868.34 2850.13,2858.5 2850.13,2675.23 2826.71,2651.81 2692.65,2651.81 2672.96,2671.49 2672.96,2858.5
  region net Efuse_OUT: 2083.14,2762.22 2096.19,2749.16 2096.19,2553.64 2135.82,2514.01 2391.72,2514.01 2411.41,2533.7 2411.41,2956.93 2391.72,2976.61 2201.42,2976.61 2088.66,2863.86 2059.32,2863.86 2050.28,2854.81 2050.28,2777.58 2065.64,2762.22
  region net Efuse_OUT: 2591.55,2038.35 2591.55,1902.38 2609.83,1884.09 2905.32,1884.09 2974.01,1952.78 2974.01,2088.95 2958.64,2104.32 2657.51,2104.32
  region net Efuse_OUT: 2066.01,1973.89 2099.99,1939.91 2099.99,1749.39 2132.87,1716.51 2388.77,1716.51 2408.46,1736.2 2408.46,2159.43 2388.77,2179.11 2198.46,2179.11 2085.71,2066.36 2056.37,2066.36 2047.32,2057.31 2047.32,1980.08 2053.51,1973.89
  region net Efuse_OUT: 2089.86,1184.95 2112.88,1161.92 2112.88,1051.95 2137.04,1027.79 2404.18,1027.79 2414.02,1037.64 2414.02,1370.48 2394.34,1390.17 2204.03,1390.17 2091.28,1277.41 2061.94,1277.41 2052.89,1268.37 2052.89,1191.13 2059.08,1184.95
  region net Efuse_OUT: 3163.01,2425.04 3131.61,2393.64 3131.61,1868.39 3157.95,1842.05 4033.05,1842.05 4045.18,1854.17 4045.18,2405.35 4025.49,2425.04
  region net Efuse_IN: 1328.73,2868.34 1486.21,2868.34 1496.05,2858.5 1496.05,2675.23 1472.63,2651.81 1338.57,2651.81 1318.89,2671.49 1318.89,2858.5
  region net Efuse_IN: 1328.73,2035.16 1486.21,2035.16 1496.05,2025.31 1496.05,1842.05 1472.63,1818.62 1338.57,1818.62 1318.89,1838.31 1318.89,2025.31
  region net Efuse_IN: 1486.21,1382.12 1328.73,1382.12 1318.89,1391.97 1318.89,1575.23 1342.31,1598.66 1476.37,1598.66 1496.05,1578.97 1496.05,1391.97
  region net Efuse_IN: 2029.53,2940.34 2029.53,2980.47 2044.97,2995.92 2044.97,3065.99 2038.7,3072.26 2038.7,3137.66 2044.97,3143.93 2088.87,3143.93 2101.36,3131.45 2101.36,3113.73 2101.36,2918.57 2088.28,2905.49 2053.5,2905.49 2027.55,2879.54 2027.55,2775.96 2027.55,2756.74 2020.9,2750.1 1949.77,2750.1 1944.04,2744.36 1944.04,2717.55 1937.11,2710.62 1858.63,2710.62 1843.18,2695.17 1843.18,2666.98 1836.45,2660.24 1670.92,2660.24 1651.04,2680.12 1651.04,2787.58 1699.76,2836.3 1892.21,2836.3 1904.13,2848.23 1904.13,2923.3 1915.86,2935.02 2024.21,2935.02
  region net Efuse_IN: 2033.37,2343.1 2036.7,2346.43 2085.91,2346.43 2098.4,2333.95 2098.4,2316.23 2098.4,2121.07 2085.33,2107.99 2050.55,2107.99 2024.6,2082.04 2024.6,1978.46 2024.6,1959.24 2017.95,1952.6 1946.82,1952.6 1941.09,1946.86 1941.09,1920.05 1934.16,1913.12 1855.68,1913.12 1840.23,1897.67 1840.23,1869.48 1833.5,1862.74 1667.96,1862.74 1648.08,1882.62 1648.08,1990.08 1696.8,2038.8 1889.25,2038.8 1901.18,2050.73 1901.18,2125.8 1912.9,2137.52 2021.26,2137.52 2033.37,2149.63
  region net Efuse_IN: 2037.06,1552.28 2042.27,1557.49 2091.48,1557.49 2103.97,1545 2103.97,1527.28 2103.97,1332.12 2090.9,1319.05 2056.12,1319.05 2030.17,1293.09 2030.17,1189.52 2030.17,1170.3 2023.52,1163.65 1952.39,1163.65 1946.66,1157.92 1946.66,1131.1 1939.73,1124.17 1861.25,1124.17 1845.8,1108.73 1845.8,1080.53 1839.06,1073.8 1673.53,1073.8 1653.65,1093.68 1653.65,1201.13 1702.37,1249.86 1894.82,1249.86 1906.75,1261.78 1906.75,1336.85 1918.47,1348.58 2026.83,1348.58 2037.06,1358.81
  region net Efuse_IN: 190.85,2419.05 155.94,2384.14 155.94,1882.95 196.84,1842.05 1050.86,1842.05 1062.98,1854.17 1062.98,2405.35 1049.29,2419.05
  text ".Layer_Name" at 493.75,-1004.76 h60
POWER1:
  region net Efuse_IN: 2103.97,1332.12 2103.97,1304.99 2086.48,1287.5 2062.51,1287.5 2045.07,1270.06 2045.07,1172.49 2036.23,1163.65 1952.39,1163.65 1946.66,1157.92 1946.66,1131.1 1939.73,1124.17 1861.25,1124.17 1845.8,1108.73 1845.8,1080.53 1839.06,1073.8 1673.53,1073.8 1653.65,1093.68 1653.65,1201.13 1702.37,1249.86 1894.82,1249.86 1906.75,1261.78 1906.75,1336.85 1918.47,1348.58 2026.83,1348.58 2039.56,1361.32 2039.56,1550.99 2046.07,1557.49 2091.48,1557.49 2103.97,1545 2103.97,1527.28
  region net Efuse_IN: 2101.36,2918.57 2101.36,2891.43 2083.86,2873.94 2059.9,2873.94 2042.45,2856.5 2042.45,2758.93 2033.62,2750.1 1949.77,2750.1 1944.04,2744.36 1944.04,2717.55 1937.11,2710.62 1858.63,2710.62 1843.18,2695.17 1843.18,2666.98 1836.45,2660.24 1670.92,2660.24 1651.04,2680.12 1651.04,2787.58 1699.76,2836.3 1892.21,2836.3 1904.13,2848.23 1904.13,2923.3 1915.86,2935.02 2024.21,2935.02 2036.95,2947.76 2036.95,3137.43 2043.45,3143.93 2088.87,3143.93 2101.36,3131.45 2101.36,3113.73
  region net Efuse_OUT: 2170.34,1035.95 2178.5,1027.79 2404.18,1027.79 2414.02,1037.64 2414.02,1370.48 2394.34,1390.17 2204.03,1390.17 2091.28,1277.41 2066.55,1277.41 2052.89,1263.76 2052.89,1191.13 2059.08,1184.95 2128.98,1184.95 2170.34,1143.59
  region net Efuse_OUT: 2086.09,1973.89 2118.64,1941.34 2118.64,1730.75 2132.88,1716.51 2388.79,1716.51 2408.47,1736.2 2408.47,2159.43 2388.79,2179.11 2198.48,2179.11 2082.02,2062.66 2057.45,2062.66 2047.34,2052.54 2047.34,1980.08 2053.53,1973.89
  region net Efuse_OUT: 2089.03,2771.39 2110.72,2749.7 2110.72,2539.11 2135.82,2514.01 2391.72,2514.01 2411.41,2533.7 2411.41,2956.93 2391.72,2976.61 2201.42,2976.61 2086.86,2862.05 2062.43,2862.05 2050.28,2849.9 2050.28,2777.58 2056.46,2771.39
  region net Efuse_IN: 2098.42,2121.07 2098.42,2093.93 2080.93,2076.44 2056.96,2076.44 2039.52,2059 2039.52,1961.43 2030.68,1952.6 1946.84,1952.6 1941.1,1946.86 1941.1,1920.05 1934.18,1913.12 1855.69,1913.12 1840.25,1897.67 1840.25,1869.48 1833.51,1862.74 1667.98,1862.74 1648.1,1882.62 1648.1,1990.08 1696.82,2038.8 1889.27,2038.8 1901.2,2050.73 1901.2,2125.8 1912.92,2137.52 2021.28,2137.52 2034.01,2150.26 2034.01,2339.93 2040.51,2346.43 2085.93,2346.43 2098.42,2333.95 2098.42,2316.23
  text ".Layer_Name" at 511.81,-1003.94 h60
GND1:
  text ".Layer_Name" at 511.81,-1004.76 h60
SIGNAL1:
  region net Efuse_IN: 1860.07,2807.11 1677.82,2807.11 1651.04,2780.32 1651.04,2680.12 1670.92,2660.24 1800.93,2660.24 1851.3,2710.62 2000.97,2710.62 2027.55,2737.2 2027.55,2906.51 2006.5,2927.57 1909.44,2927.57 1889.76,2907.88 1889.76,2836.79
  region net Efuse_IN: 1862.69,1220.66 1680.44,1220.66 1653.65,1193.88 1653.65,1093.68 1673.53,1073.8 1803.54,1073.8 1853.92,1124.17 2003.58,1124.17 2030.17,1150.76 2030.17,1320.07 2009.11,1341.12 1912.06,1341.12 1892.37,1321.44 1892.37,1250.35
  region net Efuse_OUT: 2113.74,2524.11 2404.52,2524.11 2411.41,2531 2411.41,2956.93 2396.11,2972.23 2177.48,2972.23 2089.29,2884.04 2089.29,2548.57
  region net Efuse_OUT: 2095.36,1317.57 2095.36,1161.8 2224.25,1032.92 2393.67,1032.92 2414.02,1053.27 2414.02,1370.48 2394.34,1390.17 2167.96,1390.17
  region net Efuse_OUT: 2086.34,2086.54 2086.34,1988.47 2110.79,1964.01 2110.79,1755.36 2139.54,1726.61 2401.57,1726.61 2408.46,1733.5 2408.46,2159.43 2393.15,2174.73 2174.53,2174.73
  region net Efuse_IN: 1857.12,2009.61 1674.87,2009.61 1648.08,1982.82 1648.08,1882.62 1667.96,1862.74 1797.97,1862.74 1848.35,1913.12 1998.02,1913.12 2024.6,1939.7 2024.6,2109.01 2003.54,2130.07 1906.49,2130.07 1886.8,2110.38 1886.8,2039.29
  text ".Layer_Name" at 511.81,-1004.76 h60
SIGNAL2:
  region net Efuse_IN: 1862.69,1220.66 1680.44,1220.66 1653.65,1193.88 1653.65,1093.68 1673.53,1073.8 1803.52,1073.8 1871.6,1141.87 2010.63,1141.87 2030.17,1161.41 2030.17,1320.07 2009.11,1341.12 1912.06,1341.12 1892.37,1321.44 1892.37,1250.35
  region net Efuse_IN: 1860.07,2807.11 1677.82,2807.11 1651.04,2780.32 1651.04,2680.12 1670.92,2660.24 1800.91,2660.24 1868.98,2728.32 2008.01,2728.32 2027.55,2747.85 2027.55,2906.51 2006.5,2927.57 1909.44,2927.57 1889.76,2907.88 1889.76,2836.79
  region net Efuse_OUT: 2086.34,2086.54 2086.34,1988.47 2122.38,1952.42 2122.38,1743.77 2139.54,1726.61 2401.57,1726.61 2408.46,1733.5 2408.46,2159.43 2393.15,2174.73 2174.53,2174.73
  region net Efuse_OUT: 2095.36,1317.57 2095.36,1161.8 2224.25,1032.92 2393.67,1032.92 2414.02,1053.27 2414.02,1370.48 2394.34,1390.17 2167.96,1390.17
  region net Efuse_OUT: 2113.74,2524.11 2404.52,2524.11 2411.41,2531 2411.41,2956.93 2396.11,2972.23 2177.48,2972.23 2089.29,2884.04 2089.29,2548.57
  region net Efuse_IN: 1857.13,2009.61 1674.88,2009.61 1648.1,1982.82 1648.1,1882.62 1667.98,1862.74 1797.97,1862.74 1866.05,1930.82 2005.08,1930.82 2024.61,1950.35 2024.61,2109.01 2003.56,2130.07 1906.5,2130.07 1886.82,2110.38 1886.82,2039.29
  text ".Layer_Name" at 511.81,-1004.76 h60
GND2:
  text ".Layer_Name" at 511.81,-1004.76 h60
POWER2:
  region net Efuse_OUT: 2118.58,1730.81 2132.88,1716.51 2193.29,1716.51 2193.49,1716.71 2389.36,1716.71 2389.56,1716.51 2408.47,1735.43 2408.47,2159.43 2388.79,2179.11 2198.1,2179.11 2135.29,2116.3 2050.01,2116.3 2047.31,2113.6 2047.31,2108.56 2047.31,2021.77 2056.91,2011.79 2088.8,2011.79 2118.58,1982.01
  region net Efuse_OUT: 2170.34,1144.42 2170.34,1035.95 2178.5,1027.79 2404.18,1027.79 2414.02,1037.64 2414.02,1370.48 2394.34,1390.17 2203.65,1390.17 2140.84,1327.36 2055.56,1327.36 2052.86,1324.66 2052.86,1319.62 2052.86,1232.83 2062.47,1222.85 2091.92,1222.85
  region net Efuse_OUT: 2121.52,2528.31 2135.82,2514.01 2196.23,2514.01 2196.43,2514.21 2392.29,2514.21 2392.49,2514.01 2411.41,2532.93 2411.41,2956.93 2391.72,2976.61 2201.03,2976.61 2138.22,2913.8 2052.94,2913.8 2050.25,2911.1 2050.24,2906.06 2050.24,2819.27 2059.85,2809.29 2091.74,2809.29 2121.52,2779.51
  region net Efuse_IN: 1952.49,2127.68 1927.77,2152.39 1927.77,2184.02 1905.09,2206.7 1712.04,2206.67 1699.81,2194.45 1699.81,2041.91 1648.1,1990.2 1648.1,1882.62 1667.98,1862.74 1833.51,1862.74 1840.25,1869.48 1840.25,1959.14 1791.05,2008.34 1791.05,2063.31 1801.28,2073.54 1886.32,2073.54 1900.21,2059.65 1900.21,1984.96 1911.74,1973.43 2016.4,1973.43 2019.67,1976.69 2019.66,2110.39 2002.38,2127.68
  region net Efuse_IN: 1958.04,1338.73 1933.32,1363.45 1933.32,1395.07 1910.64,1417.76 1717.59,1417.73 1705.36,1405.5 1705.36,1252.97 1653.65,1201.26 1653.65,1093.68 1673.53,1073.8 1839.06,1073.8 1845.8,1080.53 1845.8,1170.19 1796.6,1219.39 1796.6,1274.36 1806.84,1284.6 1891.87,1284.6 1905.76,1270.71 1905.76,1196.02 1917.3,1184.49 2021.95,1184.49 2025.22,1187.75 2025.22,1321.45 2007.93,1338.73
  region net Efuse_IN: 1784.51,2815.31 1784.51,2921.18 1793.67,2930.33 1834.41,2930.33 1847.4,2917.35 1847.4,2881.89 1858.25,2871.04 1889.26,2871.04 1903.15,2857.15 1903.15,2782.46 1914.68,2770.93 2019.34,2770.93 2022.6,2774.19 2022.6,2919.57 2007.15,2935.02 1945.58,2935.02 1930.71,2949.89 1930.71,2981.52 1908.02,3004.2 1714.97,3004.17 1692.9,2982.1 1692.9,2829.57 1651.04,2787.7 1651.04,2680.12 1670.92,2660.24 1836.45,2660.24 1843.18,2666.98 1843.18,2756.64
  text ".Layer_Name" at 511.81,-1004.76 h60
